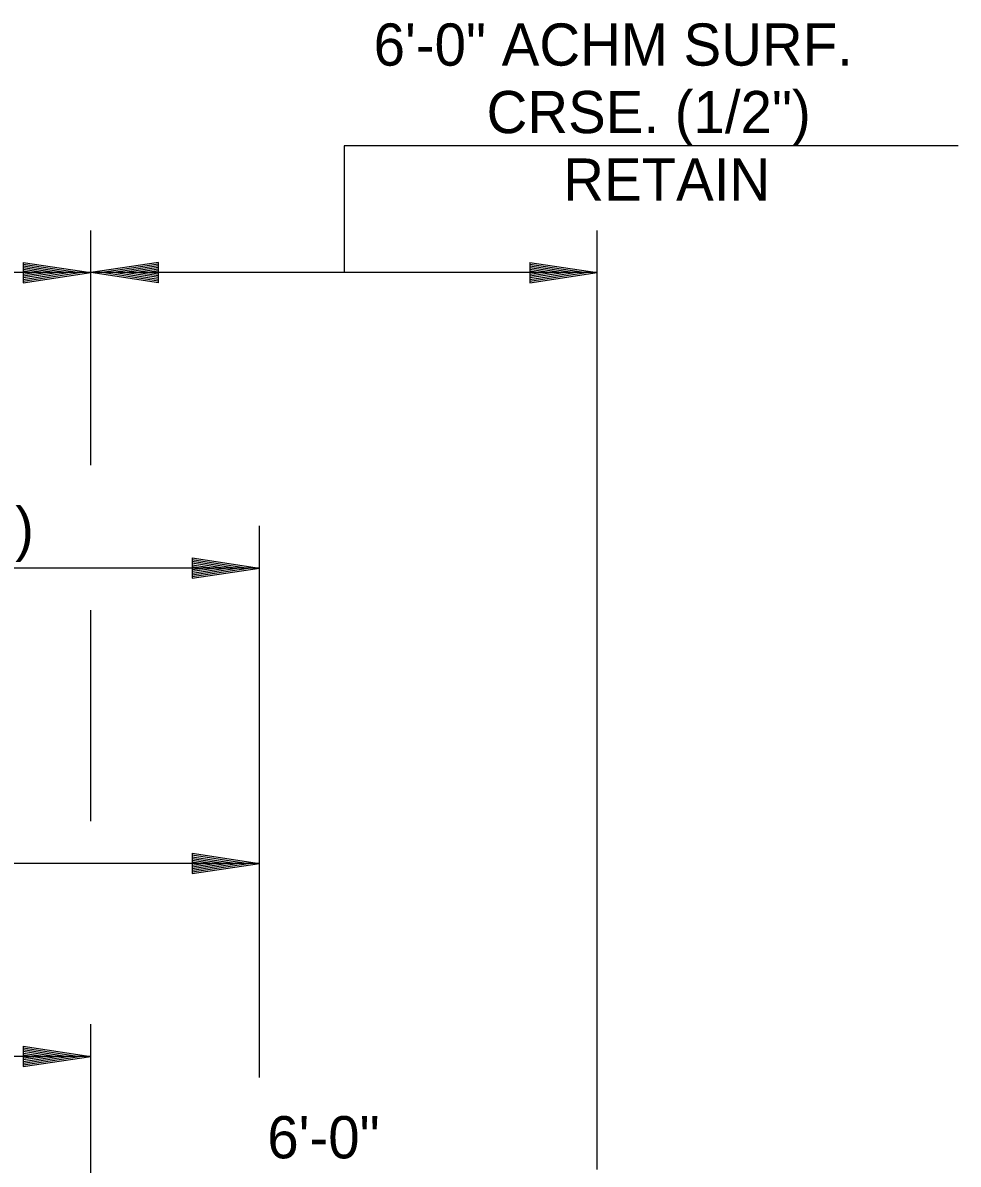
# Model space of a CAD drawing. Extents: x 60325 to 61047, y 53669 to 53767.
# Drawn here: x 60774.27 to 60785.35, y 53745.12 to 53758.64 of the extents above; entities that cross this region are included whole.
import ezdxf

# ---------------------------------------------------------------- set-up
doc = ezdxf.new("R2010")
doc.units = 0
doc.layers.add('R_Border', color=7, linetype='Continuous')
doc.layers.add('R_Border Prem', color=7, linetype='Continuous')

msp = doc.modelspace()

# ---------------------------------------------------------------- linework, layer by layer
at = {"layer": 'R_Border'}
for p, q in [((60775.077, 53740.412), (60775.077, 53746.774)), ((60774.277, 53746.514), (60775.077, 53746.394)), ((60774.277, 53746.514), (60774.277, 53746.274)), ((60774.277, 53746.494), (60774.943, 53746.394)), ((60774.277, 53746.474), (60774.806, 53746.394)), ((60774.277, 53746.454), (60774.672, 53746.394)), ((60774.277, 53746.433), (60774.537, 53746.394)), ((60774.277, 53746.413), (60774.403, 53746.394)), ((60775.077, 53746.394), (60760.077, 53746.394)), ((60774.277, 53746.274), (60775.077, 53746.394)), ((60774.277, 53746.355), (60774.537, 53746.394)), ((60774.277, 53746.315), (60774.806, 53746.394)), ((60774.277, 53746.294), (60774.943, 53746.394)), ((60774.277, 53746.335), (60774.672, 53746.394)), ((60774.277, 53746.376), (60774.403, 53746.394))]:
    msp.add_line(p, q, dxfattribs=at)
at = {"layer": 'R_Border Prem'}
for p, q in [((60778.077, 53757.18), (60778.077, 53755.68)), ((60785.353, 53757.18), (60778.077, 53757.18)), ((60775.077, 53753.4), (60775.077, 53756.18)), ((60781.077, 53745.055), (60781.077, 53756.18)), ((60774.277, 53755.8), (60775.077, 53755.68)), ((60774.277, 53755.8), (60774.277, 53755.56)), ((60774.277, 53755.78), (60774.943, 53755.68)), ((60774.277, 53755.76), (60774.806, 53755.68)), ((60774.277, 53755.74), (60774.672, 53755.68)), ((60775.877, 53755.8), (60775.077, 53755.68)), ((60775.877, 53755.78), (60775.21, 53755.68)), ((60775.877, 53755.76), (60775.348, 53755.68)), ((60775.877, 53755.74), (60775.481, 53755.68)), ((60775.877, 53755.56), (60775.877, 53755.8)), ((60780.277, 53755.8), (60781.077, 53755.68)), ((60780.277, 53755.8), (60780.277, 53755.56)), ((60780.277, 53755.78), (60780.943, 53755.68)), ((60780.277, 53755.76), (60780.806, 53755.68)), ((60780.277, 53755.74), (60780.672, 53755.68)), ((60775.077, 53755.68), (60760.077, 53755.68)), ((60774.277, 53755.719), (60774.537, 53755.68)), ((60774.277, 53755.699), (60774.403, 53755.68)), ((60774.277, 53755.56), (60775.077, 53755.68)), ((60774.277, 53755.641), (60774.537, 53755.68)), ((60774.277, 53755.6), (60774.806, 53755.68)), ((60774.277, 53755.58), (60774.943, 53755.68)), ((60774.277, 53755.62), (60774.672, 53755.68)), ((60774.277, 53755.661), (60774.403, 53755.68)), ((60781.077, 53755.68), (60775.077, 53755.68)), ((60775.877, 53755.56), (60775.077, 53755.68)), ((60775.877, 53755.58), (60775.21, 53755.68)), ((60775.877, 53755.6), (60775.348, 53755.68)), ((60775.877, 53755.62), (60775.481, 53755.68)), ((60775.877, 53755.719), (60775.617, 53755.68)), ((60775.877, 53755.641), (60775.617, 53755.68)), ((60775.877, 53755.699), (60775.75, 53755.68)), ((60775.877, 53755.661), (60775.75, 53755.68)), ((60780.277, 53755.719), (60780.537, 53755.68)), ((60780.277, 53755.699), (60780.403, 53755.68)), ((60780.277, 53755.56), (60781.077, 53755.68)), ((60780.277, 53755.641), (60780.537, 53755.68)), ((60780.277, 53755.6), (60780.806, 53755.68)), ((60780.277, 53755.58), (60780.943, 53755.68)), ((60780.277, 53755.62), (60780.672, 53755.68)), ((60780.277, 53755.661), (60780.403, 53755.68)), ((60777.077, 53746.884), (60777.077, 53752.68)), ((60776.277, 53752.3), (60777.077, 53752.18)), ((60776.277, 53752.3), (60776.277, 53752.06)), ((60776.277, 53752.28), (60776.943, 53752.18)), ((60776.277, 53752.26), (60776.806, 53752.18)), ((60776.277, 53752.24), (60776.672, 53752.18)), ((60776.277, 53752.219), (60776.537, 53752.18)), ((60777.077, 53752.18), (60758.077, 53752.18)), ((60776.277, 53752.199), (60776.403, 53752.18)), ((60776.277, 53752.06), (60777.077, 53752.18)), ((60776.277, 53752.141), (60776.537, 53752.18)), ((60776.277, 53752.1), (60776.806, 53752.18)), ((60776.277, 53752.08), (60776.943, 53752.18)), ((60776.277, 53752.12), (60776.672, 53752.18)), ((60776.277, 53752.161), (60776.403, 53752.18)), ((60775.077, 53749.18), (60775.077, 53751.68)), ((60776.277, 53748.8), (60777.077, 53748.68)), ((60776.277, 53748.8), (60776.277, 53748.56)), ((60776.277, 53748.78), (60776.943, 53748.68)), ((60776.277, 53748.76), (60776.806, 53748.68)), ((60776.277, 53748.74), (60776.672, 53748.68)), ((60776.277, 53748.719), (60776.537, 53748.68)), ((60776.277, 53748.699), (60776.403, 53748.68)), ((60777.077, 53748.68), (60758.077, 53748.68)), ((60776.277, 53748.56), (60777.077, 53748.68)), ((60776.277, 53748.641), (60776.537, 53748.68)), ((60776.277, 53748.6), (60776.806, 53748.68)), ((60776.277, 53748.58), (60776.943, 53748.68)), ((60776.277, 53748.62), (60776.672, 53748.68)), ((60776.277, 53748.661), (60776.403, 53748.68)), ((60777.077, 53746.145), (60777.077, 53746.884))]:
    msp.add_line(p, q, dxfattribs=at)

# ---------------------------------------------------------------- texts
for s, p in [('6\'-0" ACHM SURF.', (60778.428, 53758.132)), ('CRSE. (1/2")', (60779.766, 53757.332)), ('RETAIN', (60780.674, 53756.532)), (' EXISTING 19\'-0" ACHM SURFACE COURSE (3/8")', (60758.828, 53752.401)), ('6\'-0"', (60777.168, 53745.186))]:
    msp.add_text(s, height=0.5, dxfattribs=at).set_placement(p)

doc.saveas('drawing.dxf')
